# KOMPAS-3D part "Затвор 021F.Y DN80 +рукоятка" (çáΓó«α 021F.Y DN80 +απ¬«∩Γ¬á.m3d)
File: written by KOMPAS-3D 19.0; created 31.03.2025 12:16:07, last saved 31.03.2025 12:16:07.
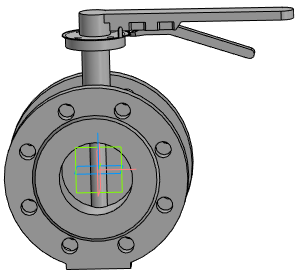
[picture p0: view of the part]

Document properties: Автор: Евгений; Полное имя файла: Затвор 021F.Y DN80 +рукоятка.a3d

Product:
- Part/product: Затвор 021F.Y DN80 +рукоятка
    Масса: 12.0212

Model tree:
1. Операция без истории:1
